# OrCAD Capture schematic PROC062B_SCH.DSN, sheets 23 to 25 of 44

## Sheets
23 22. RGMII ETHERNET PHY - MCU: size C; title: RGMII ETHERNET PHY - MCU
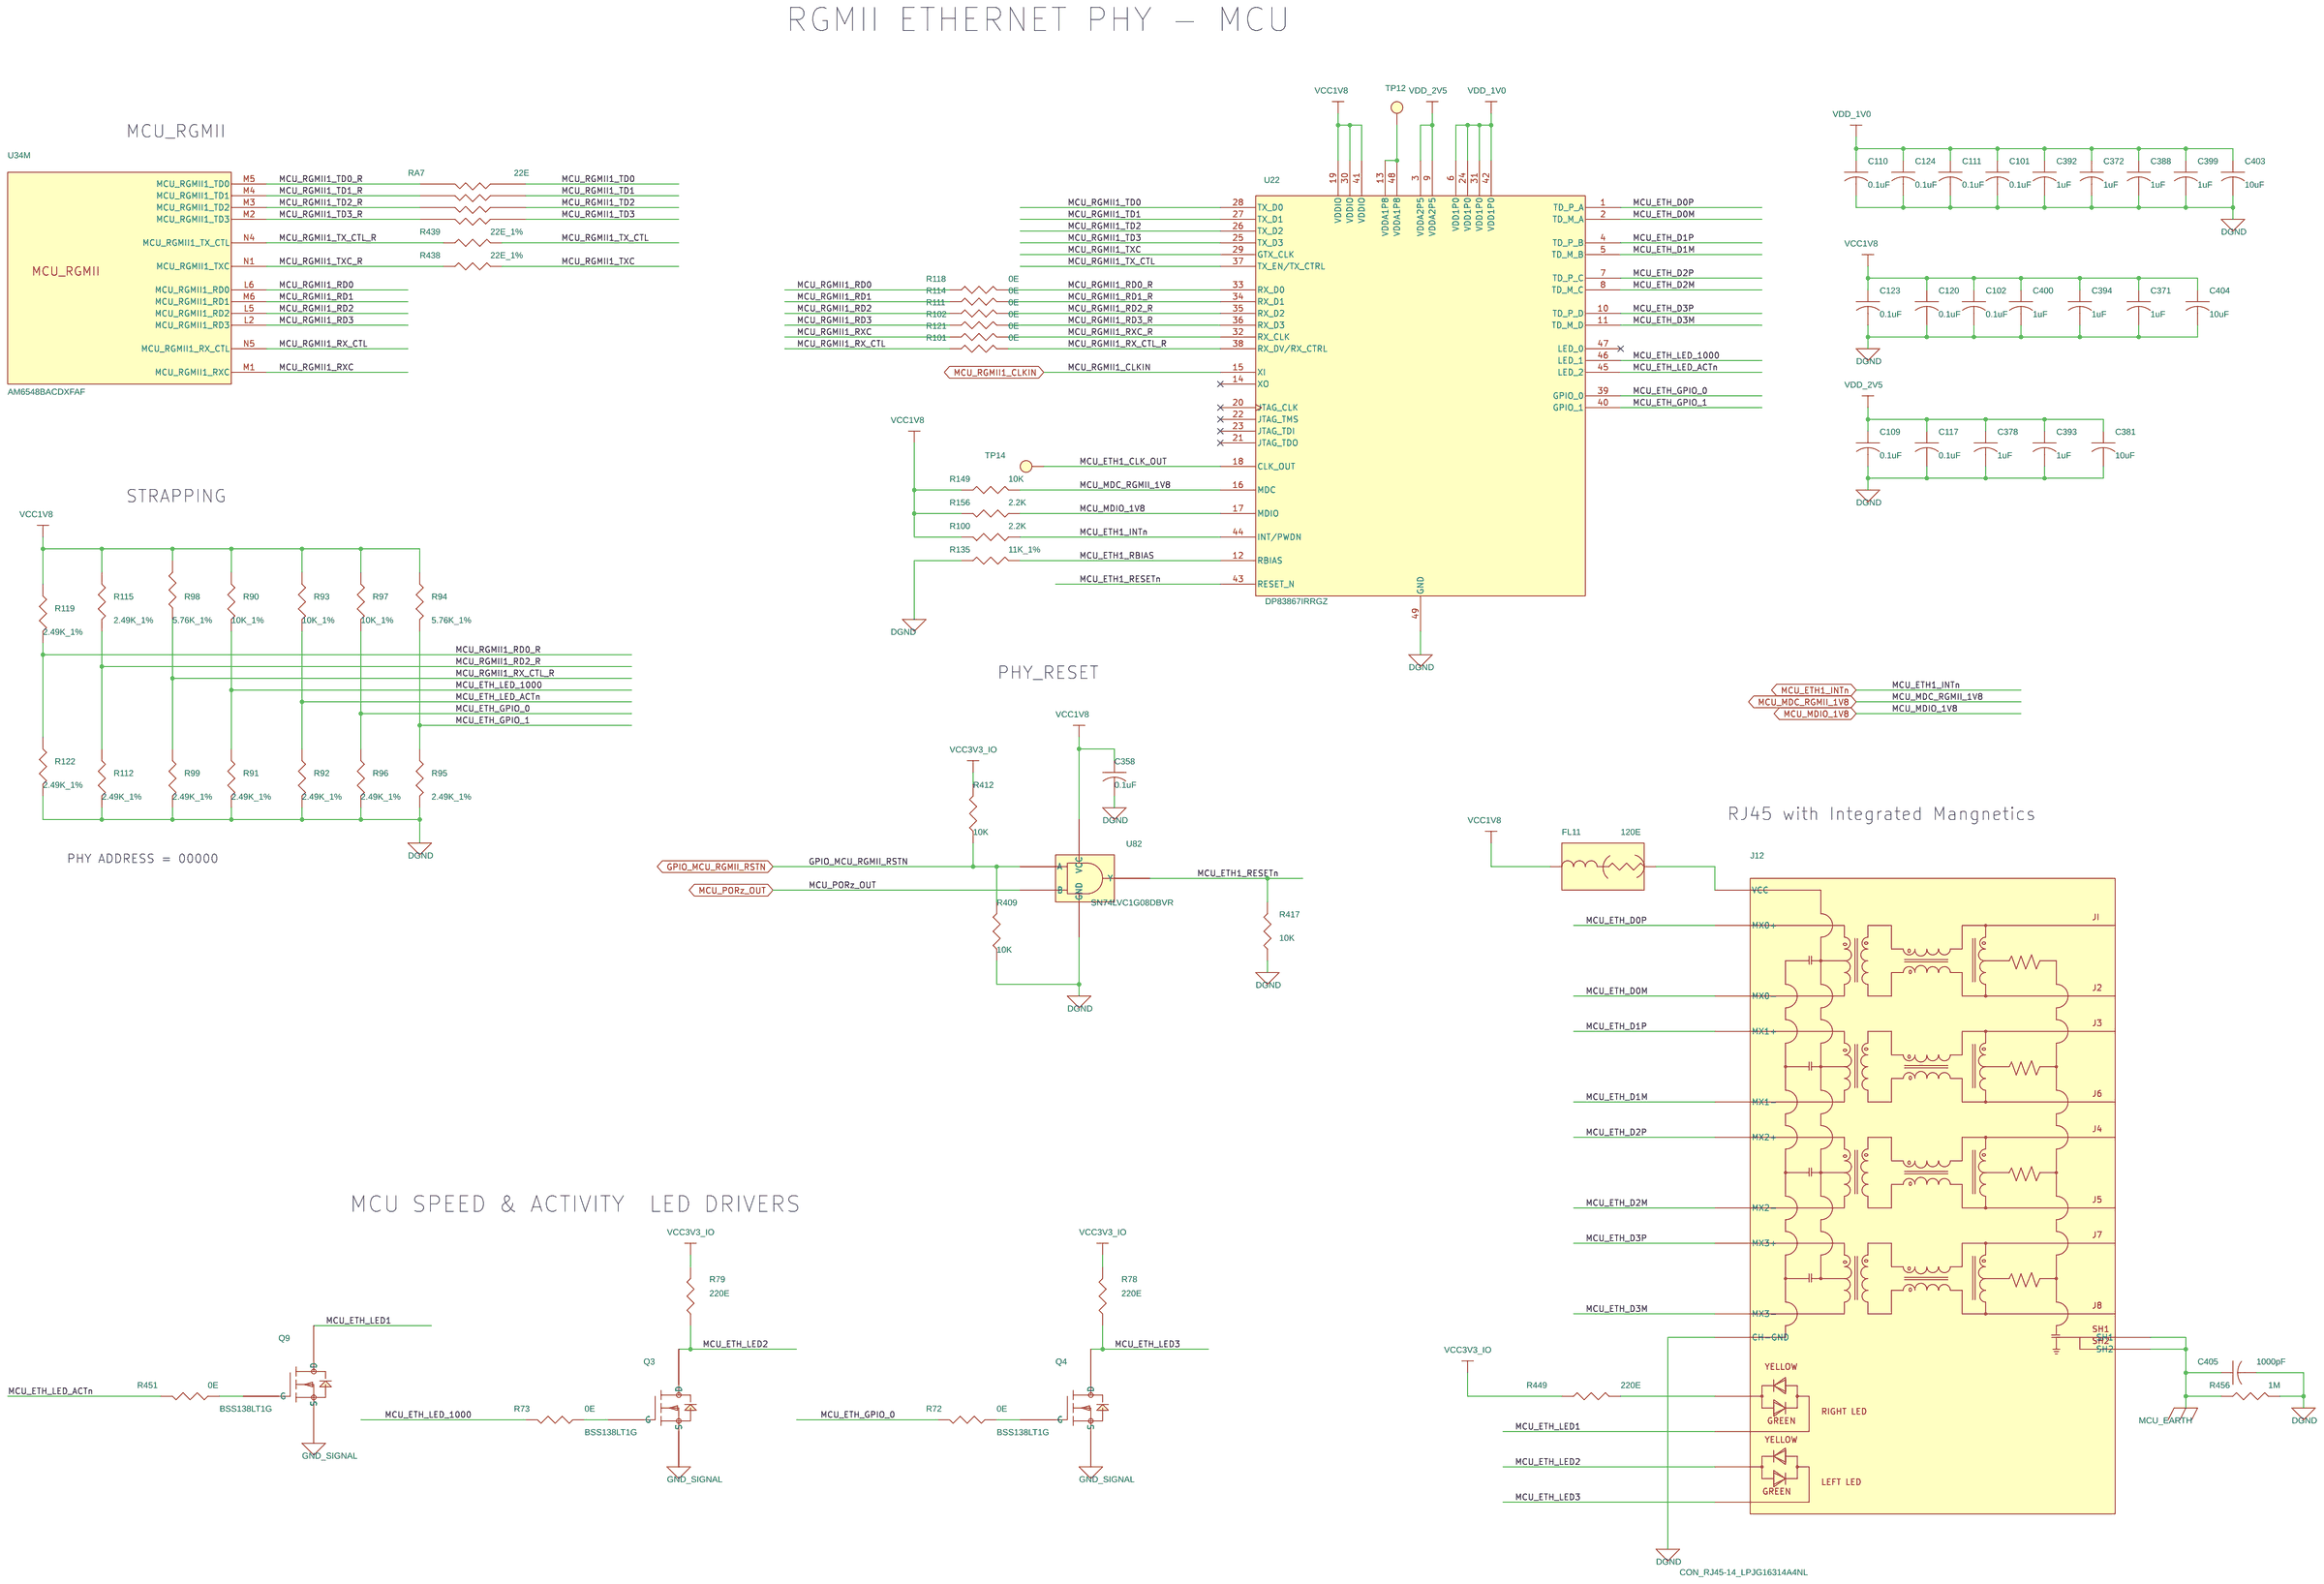
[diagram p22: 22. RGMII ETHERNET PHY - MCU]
24 23. TEST AUTOMATION: size C; title: TEST AUTOMATION
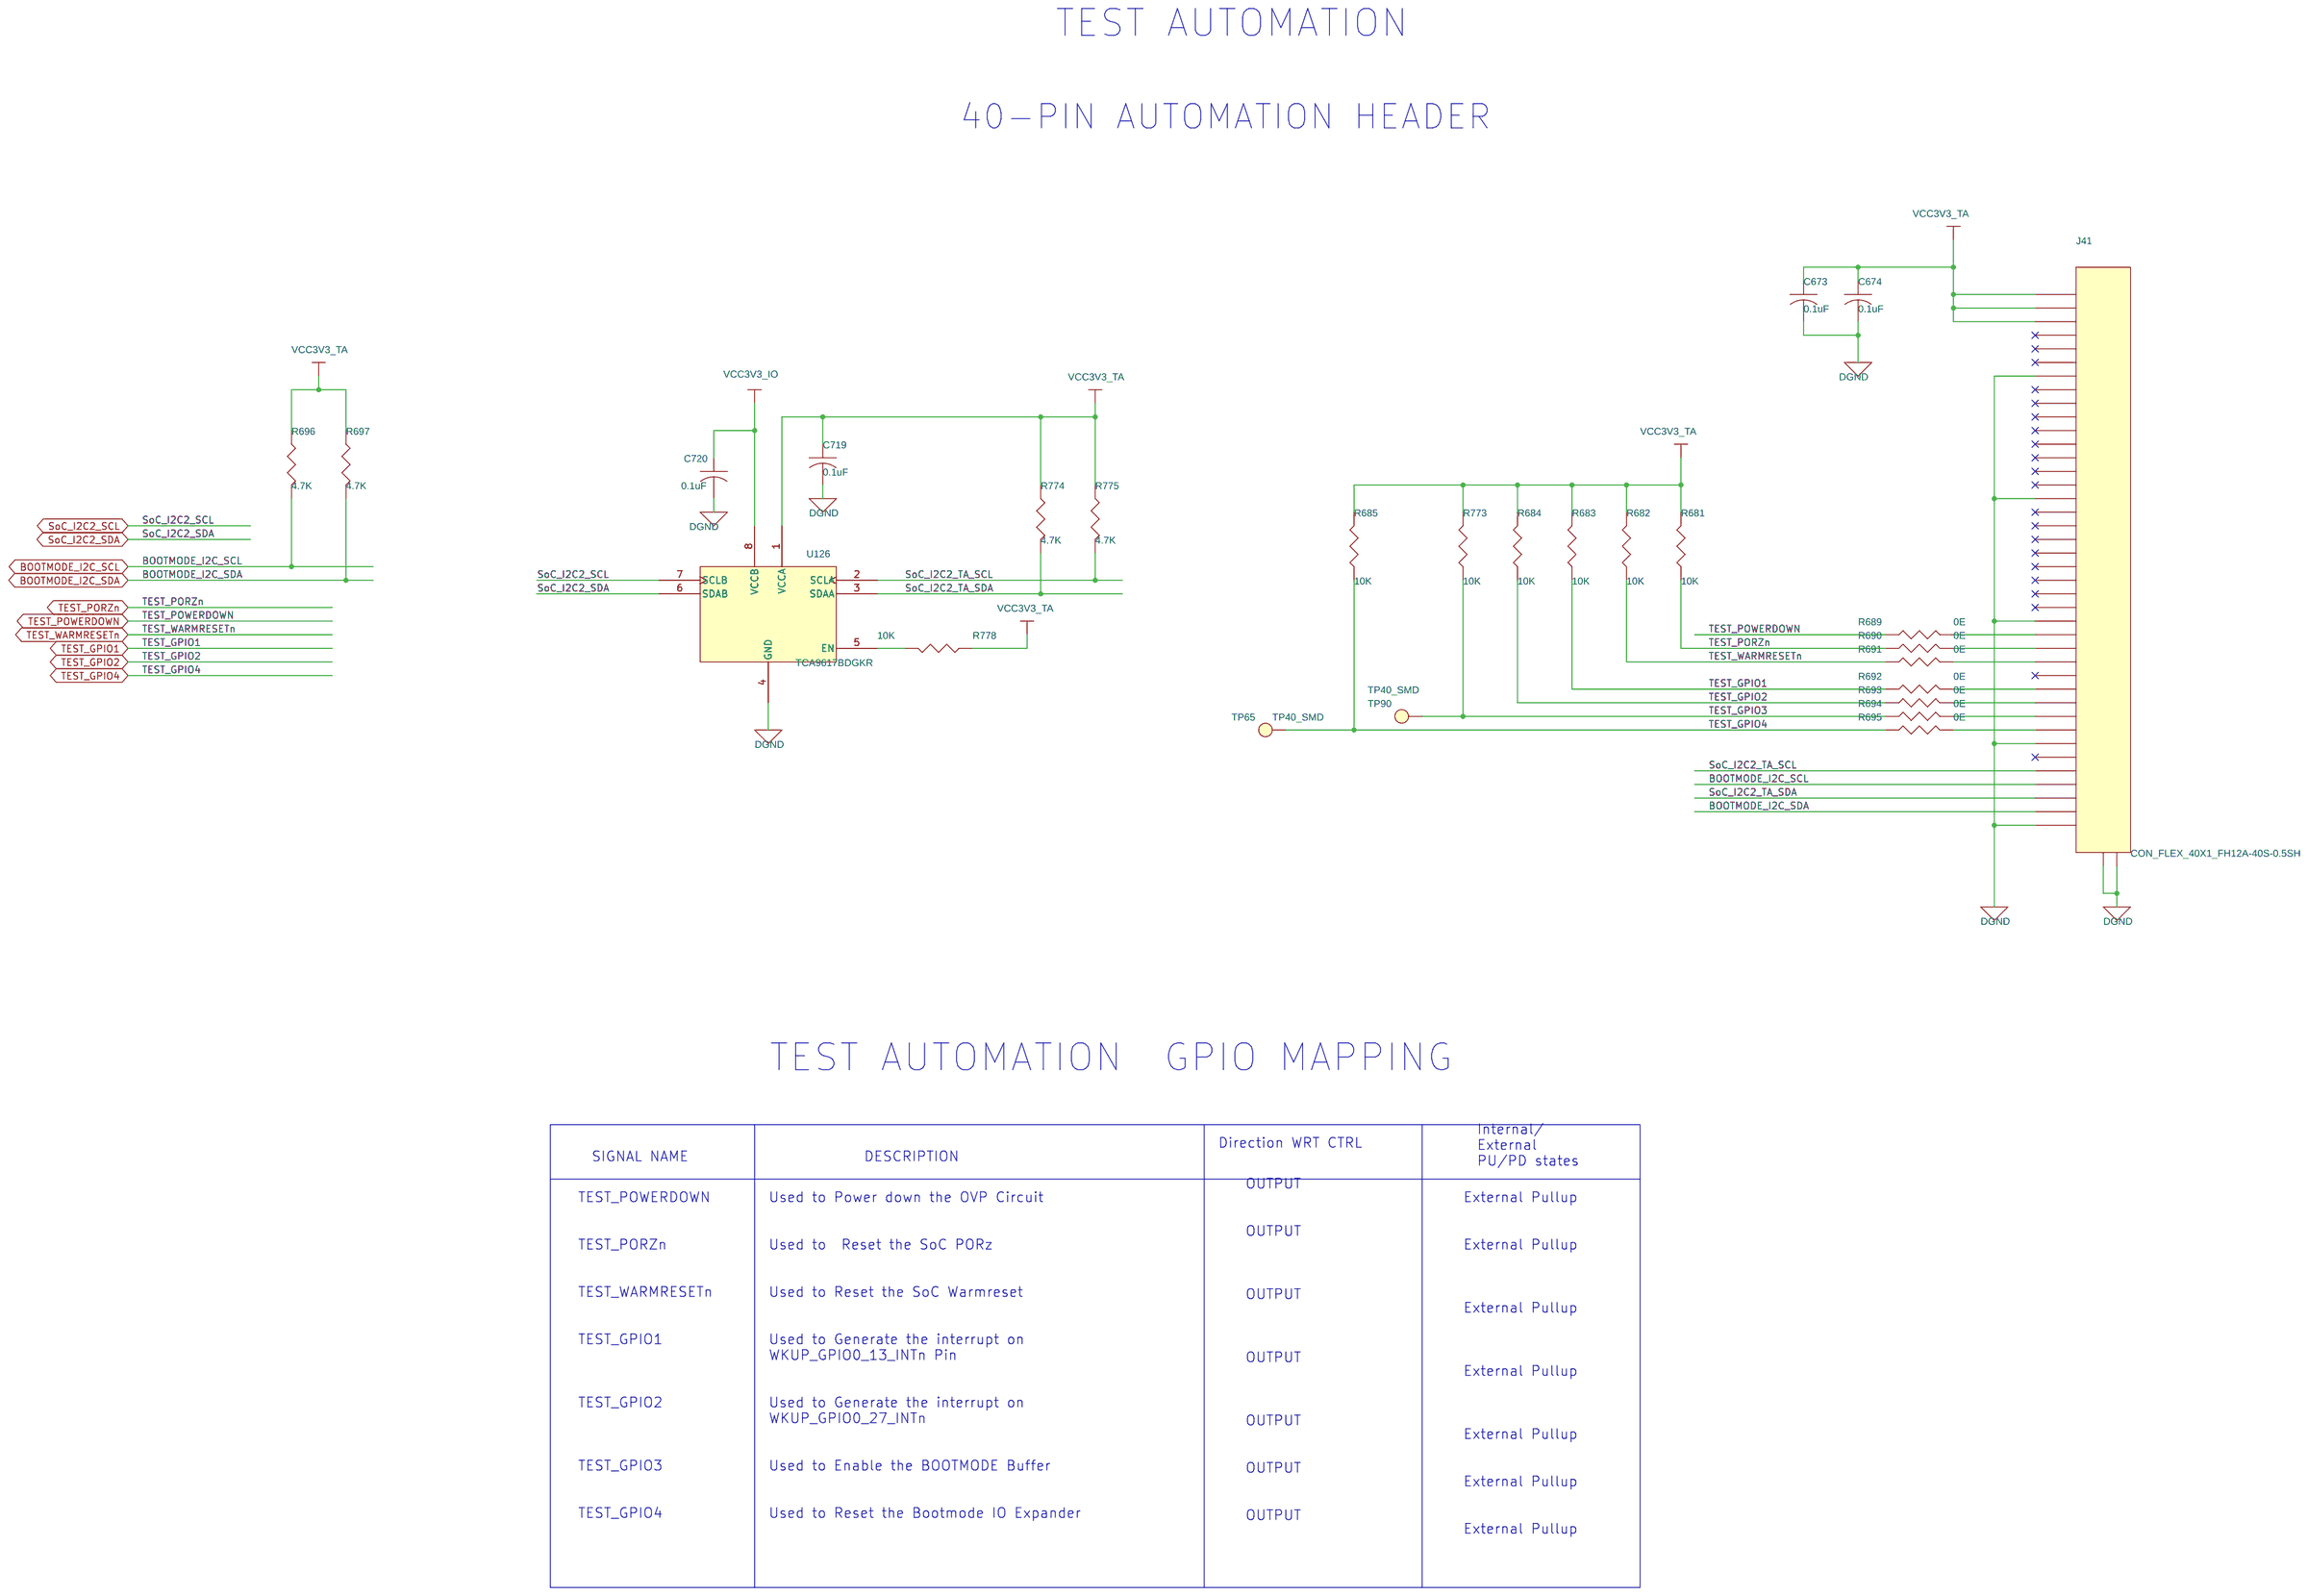
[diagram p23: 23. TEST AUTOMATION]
25 24. BOOT MODE BUFFER & SWITCHES: size C; title: BOOT MODE BUFFER & SWITCHES
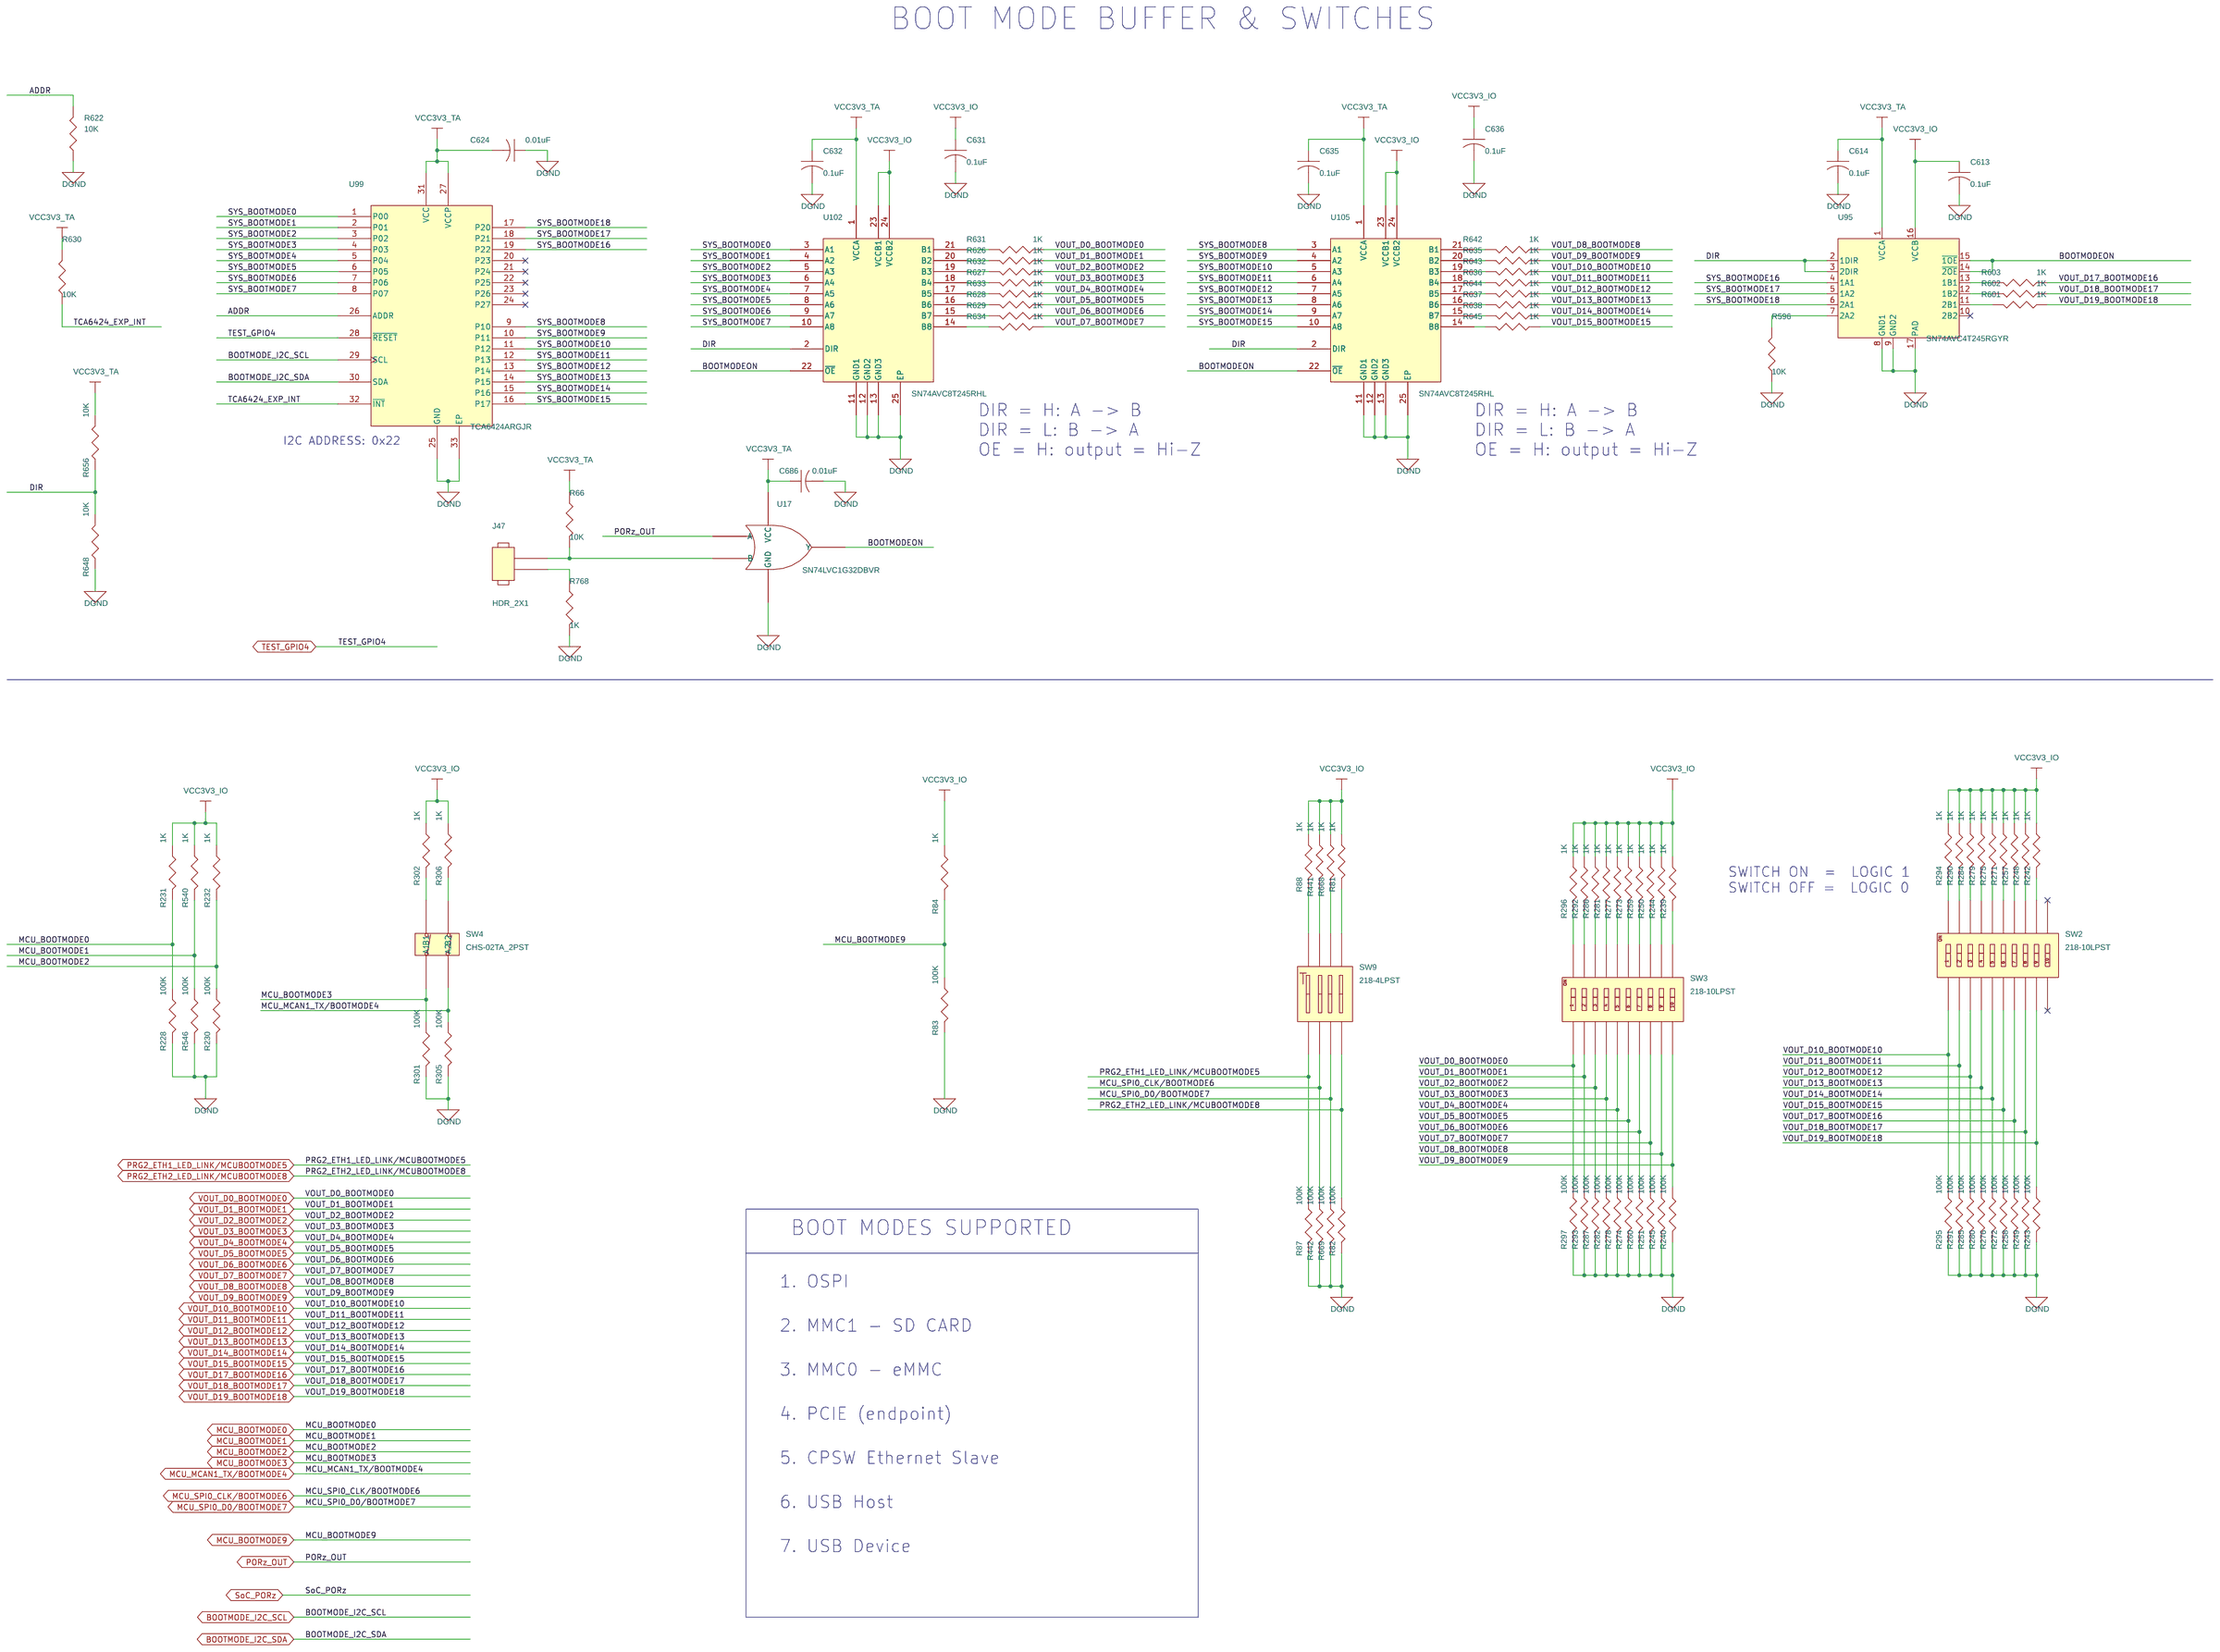
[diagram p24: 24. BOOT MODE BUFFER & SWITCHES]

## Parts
sheet 16. DDR4 ECC & TERMINATIONS
U34  AM6548BACDXFAF  [BGA784_31-49_910X910_1-7]  (sections A,B,C,D,E,F,G,H,I,J,K,L,M,N,O,P,Q,R,S)
sheet 22. RGMII ETHERNET PHY - MCU
C101  0.1uF  [CAP0201_0-5]
C102  0.1uF  [CAP0201_0-5]
C109  0.1uF  [CAP0201_0-5]
C110  0.1uF  [CAP0201_0-5]
C111  0.1uF  [CAP0201_0-5]
C117  0.1uF  [CAP0201_0-5]
C120  0.1uF  [CAP0201_0-5]
C123  0.1uF  [CAP0201_0-5]
C124  0.1uF  [CAP0201_0-5]
C358  0.1uF  [CAP0201_0-5]
C371  1uF  [CAP0402_0-75]
C372  1uF  [CAP0402_0-75]
C378  1uF  [CAP0402_0-75]
C381  10uF  [CAP0603_1]
C388  1uF  [CAP0402_0-75]
C392  1uF  [CAP0402_0-75]
C393  1uF  [CAP0402_0-75]
C394  1uF  [CAP0402_0-75]
C399  1uF  [CAP0402_0-75]
C400  1uF  [CAP0402_0-75]
C403  10uF  [CAP0603_1]
C404  10uF  [CAP0603_1]
C405  1000pF  [CAP1206]
FL11  120E  [EMIFIL_BLM15A_0402_0-6]
J12  CON_RJ45-14_LPJG16314A4NL  [CON_RJ45-14_LPJG16314A4NL_S_R_T_13-6]
Q3  BSS138LT1G  [SOT23-123]
Q4  BSS138LT1G  [SOT23-123]
Q9  BSS138LT1G  [SOT23-123]
R72  0E  [RES0402_0-5]
R73  0E  [RES0402_0-5]
R78  220E  [RES0402_0-5]
R79  220E  [RES0402_0-5]
R90  10K_1%  [RES0402_0-5]
R91  2.49K_1%  [RES0402]
R92  2.49K_1%  [RES0402]
R93  10K_1%  [RES0402_0-5]
R94  5.76K_1%  [RES0402]
R95  2.49K_1%  [RES0402]
R96  2.49K_1%  [RES0402]
R97  10K_1%  [RES0402_0-5]
R98  5.76K_1%  [RES0402]
R99  2.49K_1%  [RES0402]
R100  2.2K  [RES0402_0-5]
R101  0E  [RES0402_0-5]
R102  0E  [RES0402_0-5]
R111  0E  [RES0402_0-5]
R112  2.49K_1%  [RES0402]
R114  0E  [RES0402_0-5]
R115  2.49K_1%  [RES0402]
R118  0E  [RES0402_0-5]
R119  2.49K_1%  [RES0402]
R121  0E  [RES0402_0-5]
R122  2.49K_1%  [RES0402]
R135  11K_1%  [RES0402_0-5]
R149  10K  [RES0201]
R156  2.2K  [RES0402_0-5]
R409  10K  [RES0402_0-5]
R412  10K  [RES0402_0-5]
R417  10K  [RES0402_0-5]
R438  22E_1%  [RES0402]
R439  22E_1%  [RES0402]
R449  220E  [RES0402_0-5]
R451  0E  [RES0402_0-5]
R456  1M  [RES0603_0-75]
RA7  22E  [RESA_EXB28V_0402-4_0-5]
TP12  TP40_SMD  [TP40_SMD]
TP14  TP40_SMD  [TP40_SMD]
U22  DP83867IRRGZ  [QFN48_19-68_280X280_1]
U82  SN74LVC1G08DBVR  [SOT23-5]
sheet 23. TEST AUTOMATION
C673  0.1uF  [CAP0201_0-5]
C674  0.1uF  [CAP0201_0-5]
C719  0.1uF  [CAP0201_0-5]
C720  0.1uF  [CAP0201_0-5]
J41  CON_FLEX_40X1_FH12A-40S-0.5SH  [CON_FLEX40X1_FH12A_S_R_S]
R681  10K  [RES0402_0-5]
R682  10K  [RES0402_0-5]
R683  10K  [RES0402_0-5]
R684  10K  [RES0402_0-5]
R685  10K  [RES0402_0-5]
R689  0E  [RES0402_0-5]
R690  0E  [RES0402_0-5]
R691  0E  [RES0402_0-5]
R692  0E  [RES0402_0-5]
R693  0E  [RES0402_0-5]
R694  0E  [RES0402_0-5]
R695  0E  [RES0402_0-5]
R696  4.7K  [RES0402]
R697  4.7K  [RES0402]
R773  10K  [RES0402_0-5]
R774  4.7K  [RES0402]
R775  4.7K  [RES0402]
R778  10K  [RES0402_0-5]
TP65  TP40_SMD  [TP40_SMD]
TP90  TP40_SMD  [TP40_SMD]
U126  TCA9617BDGKR  [VSSOP8_25-59_120X120_1-1]
sheet 24. BOOT MODE BUFFER & SWITCHES
C613  0.1uF  [CAP0201_0-5]
C614  0.1uF  [CAP0201_0-5]
C624  0.01uF  [CAP0201_0-5]
C631  0.1uF  [CAP0201_0-5]
C632  0.1uF  [CAP0201_0-5]
C635  0.1uF  [CAP0201_0-5]
C636  0.1uF  [CAP0201_0-5]
C686  0.01uF  [CAP0201_0-5]
J47  HDR_2X1  [HDR_2X1_100_S_T_10-8]
R66  10K  [RES0402_0-5]
R81  1K  [RES0201]
R82  100K  [RES0402_0-5]
R83  100K  [RES0402_0-5]
R84  1K  [RES0402]
R87  100K  [RES0402_0-5]
R88  1K  [RES0201]
R228  100K  [RES0402_0-5]
R230  100K  [RES0402_0-5]
R231  1K  [RES0201]
R232  1K  [RES0201]
R239  1K  [RES0201]
R240  100K  [RES0402_0-5]
R242  1K  [RES0201]
R243  100K  [RES0402_0-5]
R244  1K  [RES0201]
R245  100K  [RES0402_0-5]
R248  1K  [RES0201]
R249  100K  [RES0402_0-5]
R250  1K  [RES0201]
R251  100K  [RES0402_0-5]
R257  1K  [RES0201]
R258  100K  [RES0402_0-5]
R259  1K  [RES0201]
R260  100K  [RES0402_0-5]
R271  1K  [RES0201]
R272  100K  [RES0402_0-5]
R273  1K  [RES0201]
R274  100K  [RES0402_0-5]
R275  1K  [RES0201]
R276  100K  [RES0402_0-5]
R277  1K  [RES0201]
R278  100K  [RES0402_0-5]
R279  1K  [RES0201]
R280  100K  [RES0402_0-5]
R281  1K  [RES0201]
R282  100K  [RES0402_0-5]
R284  1K  [RES0201]
R285  100K  [RES0402_0-5]
R286  1K  [RES0201]
R287  100K  [RES0402_0-5]
R290  1K  [RES0201]
R291  100K  [RES0402_0-5]
R292  1K  [RES0201]
R293  100K  [RES0402_0-5]
R294  1K  [RES0201]
R295  100K  [RES0402_0-5]
R296  1K  [RES0201]
R297  100K  [RES0402_0-5]
R301  100K  [RES0402_0-5]
R302  1K  [RES0201]
R305  100K  [RES0402_0-5]
R306  1K  [RES0201]
R441  1K  [RES0201]
R442  100K  [RES0402_0-5]
R540  1K  [RES0201]
R546  100K  [RES0402_0-5]
R596  10K  [RES0402_0-5]
R601  1K  [RES0201]
R602  1K  [RES0201]
R603  1K  [RES0201]
R622  10K  [RES0402_0-5]
R626  1K  [RES0201]
R627  1K  [RES0201]
R628  1K  [RES0201]
R629  1K  [RES0201]
R630  10K  [RES0402_0-5]
R631  1K  [RES0201]
R632  1K  [RES0201]
R633  1K  [RES0201]
R634  1K  [RES0201]
R635  1K  [RES0201]
R636  1K  [RES0201]
R637  1K  [RES0201]
R638  1K  [RES0201]
R642  1K  [RES0201]
R643  1K  [RES0201]
R644  1K  [RES0201]
R645  1K  [RES0201]
R648  10K  [RES0402_0-5]
R656  10K  [RES0402_0-5]
R668  1K  [RES0201]
R669  100K  [RES0402_0-5]
R768  1K  [RES0201]
SW2  218-10LPST  [SW10_50_550X230_SMD]
SW3  218-10LPST  [SW10_50_550X230_SMD]
SW4  CHS-02TA_2PST  [SW2_50x200_160x210_SMD]
SW9  218-4LPST  [SW8_218-4LPS_230X250_SMD_2-7]
U17  SN74LVC1G32DBVR  [SOT23-5_1-5]
U95  SN74AVC4T245RGYR  [QFN16_19-68_160X140]
U99  TCA6424ARGJR  [QFN32_19-68_200X200]
U102  SN74AVC8T245RHL  [QFN24_19-68_220X140_1]
U105  SN74AVC8T245RHL  [QFN24_19-68_220X140_1]

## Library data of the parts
U34 = AM654X_BGA784: IC AM65X MICRO CONTROLLER UNIT BGA784; Chkd/date: ALVY/010721; Crtd /date: MANIRAJA/010721; Custom_Duty: 15%; Customs_HS_Code: 85423100; Distributor_name: NA; Distributor_part_number: NA; Footprint Path: Y:\MIS_DATABASE\Library\ALTIUM_TOOL\PCB_FOOTPRINTS\Altium_Footprint_Lib.PcbLib; Height: 1.63MM; Library Path: Y:\MIS_DATABASE\Library\ALTIUM_TOOL\SCHEMATICS_PARTS\MS_MICROCONTROLLER_Library.schlib; Mfr_name: TEXAS INSTRUMENTS; Mistral Part No: 141221070001; Package: BGA784; Part_type: ICS\DIGITAL\MICROCONTROLLER; Project: TI_AM65X_CP; RoHS: NA; Temperature: NA; Tolerance: NA; Voltage: NA; Wattage: NA; Weight: NA; Datasheet: Y:\MIS_DATABASE\DATASHEETS\ICS\DIGITAL\MICROCONTROLLER\MAXWELLM4.PDF
C101 C102 C109-C111 C117 C120 C123 C124 C358 C613 C614 C631 C632 C635 C636 C673 C674 C719 C720 = CAP: CAP CERAMIC 0.1uF 16V 10% X5R 0201; Chkd/date: MANIRAJA/120218; Crtd /date: MANIRAJA/120218; Custom_Duty: 15%; Customs_HS_Code: 85322990; Distributor_name: DIGIKEY; Distributor_part_number: 490-16742-1-ND; Height: 0.33MM; Mfr_name: MURATA; Mfr_part_number: GRM033R61C104KE84J; Mistral Part No: 120009030072-R; Package: 0201; Part_type: CAPACITORS\CERAMIC; Project: TI_MAXIE_CPB; RoHS: RoHS; Temperature: -55°C+85°C; Tolerance: 10%; Voltage: 16V; Wattage: NA; Weight: 0.33mg; Datasheet: Y:\MIS_DATABASE\DATASHEETS\CAPACITORS\GRM033R61C104KE84.PDF
C371 C372 C378 C388 C392-C394 C399 C400 = CAP: CAP CERAMIC 1uF 16V 20% X5R 0402; Chkd/date: MANIRAJA/150218; Crtd /date: ALVY/150218; Custom_Duty: 15%; Customs_HS_Code: 85322990; Distributor_name: DIGIKEY; Distributor_part_number: 587-5514-1-ND; Footprint Path: Y:\MIS_DATABASE\Library\ALTIUM_TOOL\PCB_FOOTPRINTS\Altium_Footprint_Lib.PcbLib; Height: 0.55MM; Library Path: Y:\MIS_DATABASE\Library\ALTIUM_TOOL\SCHEMATICS_PARTS\MS_DISCRETE_Library.schlib; Mfr_name: TAIYO YUDEN; Mfr_part_number: EMK105BJ105MV-F; Mistral Part No: 120018020006-R; Package: 0402; Part_type: CAPACITORS\CERAMIC; Project: TI_MAXIE_CPB; RoHS: RoHS; Temperature: -55°C+85°C; Tolerance: 20%; Voltage: 16V; Wattage: NA; Weight: 0.65mg; Datasheet: Y:\MIS_DATABASE\DATASHEETS\CAPACITORS\EMK105BJ105MV-F.PDF
C381 C403 C404 = CAP: CAP CERAMIC 10uF 10V 10% X5R 0603; Chkd/date: MANIRAJA/230118; Crtd /date: MANIRAJA/230118; Custom_Duty: 15%; Customs_HS_Code: 85322990; Distributor_name: DIGIKEY; Distributor_part_number: 478-10766-1-ND; Height: 0.94MM; Mfr_name: AVX CORPORATION; Mfr_part_number: 0603ZD106KAT2A; Mistral Part No: 120010080001-R; Package: 0603; Part_type: CAPACITORS\CERAMIC; Project: TI_MAXIE_CPB; RoHS: RoHS; Temperature: -55°C+85°C; Tolerance: 10%; Voltage: 10V; Wattage: NA; Weight: 2mg; Datasheet: Y:\MIS_DATABASE\DATASHEETS\CAPACITORS\AVX_MLC.PDF
C405 = CAP: CAP CERAMIC 1000pF 2KV 10% X7R 1206; Chkd/date: SHREESHAIL/291106; Crtd /date: MAZHAR/281106; Custom_Duty: 15%; Customs_HS_Code: 85322990; Distributor_name: DIGIKEY; Distributor_part_number: 478-2956-1-ND; Footprint Path: Y:\MIS_DATABASE\Library\ALTIUM_TOOL\PCB_FOOTPRINTS\Altium_Footprint_Lib.PcbLib; Height: 1.50MM; Library Path: Y:\MIS_DATABASE\Library\ALTIUM_TOOL\SCHEMATICS_PARTS\MS_DISCRETE_Library.schlib; Mfr_name: AVX CORPORATION; Mfr_part_number: 1206GC102KAT1A; Mistral Part No: 120009030147-R; Package: 1206; Part_type: CAPACITORS\CERAMIC; Project: ADR1B; RoHS: RoHS; Temperature: -55°C+125°C; Tolerance: 10%; Voltage: 2KV; Weight: NA; Datasheet: Y:\MIS_DATABASE\DATASHEETS\CAPACITORS\AVX_MLC.PDF
FL11 = EMIFILTER_IND: FERRITE CHIP 120E 1.3A 0402; Chkd/date: VASANTHA/010117; Crtd /date: CHAITHANYA/150312; Custom_Duty: 24%; Customs_HS_Code: 85437099; Distributor_name: DIGIKEY; Distributor_part_number: 490-5203-1-ND; Footprint Path: Y:\MIS_DATABASE\Library\ALTIUM_TOOL\PCB_FOOTPRINTS\Altium_Footprint_Lib.PcbLib; Height: 0.55MM; Library Path: Y:\MIS_DATABASE\Library\ALTIUM_TOOL\SCHEMATICS_PARTS\MS_FILTER_Library.schlib; Mfr_name: MURATA; Mfr_part_number: BLM15PD121SN1; Mistral Part No: 130012030043-R; Package: 0402; Part_type: MISC\FILTER; Project: GEN_3-8; RoHS: RoHS; Temperature: -55°C+125°C; Tolerance: 25%; Voltage: NA; Wattage: NA; Weight: 0.65mg; Datasheet: Y:\MIS_DATABASE\DATASHEETS\DISCRETES\INDUCTORS\BLM18K-SERIES.PDF
J12 = CON_RJ45-14_LPJG16314A4NL: CON RJ-45 FEMALE 14POS RT TH; Chkd/date: VASANTHA/150714; Crtd /date: BALACHANDAR/120614; Custom_Duty: 24%; Customs_HS_Code: 85369090; Distributor_name: NA; Distributor_part_number: NA; Footprint Path: Y:\MIS_DATABASE\Library\ALTIUM_TOOL\PCB_FOOTPRINTS\Altium_Footprint_Lib.PcbLib; Height: 13.60MM; Library Path: Y:\MIS_DATABASE\Library\ALTIUM_TOOL\SCHEMATICS_PARTS\MS_CONNECTOR_Library.schlib; Mfr_name: LINK-PP; Mfr_part_number: LPJG16314A4NL; Mistral Part No: 150014060029-R; Package: THRU-HOLE; Part_type: CONNECTOR\JACK; Project: AEGIS; RoHS: RoHS; Temperature: -0°C+70°C; Tolerance: NA; Voltage: NA; Wattage: NA; Weight: NA; Datasheet: Y:\MIS_DATABASE\DATASHEETS\CONNECTORS\LPJG16314A4NL.PDF
Q3 Q4 Q9 = MOSFET_BSS138LT1G: IC MOSFET N-CHANNEL 50V, SOT23-3; Chkd/date: VASANTHA/150416; Crtd /date: JEBRAN/060416; Custom_Duty: 15%; Customs_HS_Code: 85423100; Distributor_name: MOUSER; Distributor_part_number: 863-BSS138LT1G; Height: 1.11MM; Mfr_name: ON SEMICONDUCTOR; Mistral Part No: 142016040001-R; Package: SOT23-3; Part_type: ICS\POWER\MOSFET; Project: LRDE_ABCM; RoHS: RoHS; Temperature: -55°C+150°C; Tolerance: NA; Voltage: 50V; Wattage: NA; Weight: NA; Datasheet: Y:\MIS_DATABASE\DATASHEETS\DISCRETES\TRANSISTORS_FETS\BSS138LT1G.PDF
R72 R73 R101 R102 R111 R114 R118 R121 R451 R689-R695 = RESISTOR: RES 0E 1/16W 0402; Chkd/date: VASANTHA/201216; Crtd /date: MUDDU/190810; Custom_Duty: 15%; Customs_HS_Code: 85332119; Distributor_name: DIGIKEY; Distributor_part_number: 541-0.0JCT-ND; Footprint Path: Y:\MIS_DATABASE\Library\ALTIUM_TOOL\PCB_FOOTPRINTS\Altium_Footprint_Lib.PcbLib; Height: 0.40MM; Library Path: Y:\MIS_DATABASE\Library\ALTIUM_TOOL\SCHEMATICS_PARTS\MS_DISCRETE_Library.schlib; Mfr_name: VISHAY; Mfr_part_number: CRCW04020000Z0ED; Mistral Part No: 110010080019-P; Package: 0402; Part_type: RESISTORS\FIXED; Project: PB_BUGBASE; RoHS: Pb-Free; Temperature: -55°C+155°C; Tolerance: NA; Voltage: NA; Wattage: 1/16W; Weight: 0.65g/1000pcs; Datasheet: Y:\MIS_DATABASE\DATASHEETS\RESISTORS\CRCW0603.PDF
R78 R79 R449 = RESISTOR: RES 220E 1/16W 5% 0402; Chkd/date: VASANTHA/291216; Crtd /date: GEETHA/260406; Custom_Duty: 15%; Customs_HS_Code: 85332119; Distributor_name: DIGIKEY; Distributor_part_number: P220JCT-ND; Footprint Path: Y:\MIS_DATABASE\Library\ALTIUM_TOOL\PCB_FOOTPRINTS\Altium_Footprint_Lib.PcbLib; Height: 0.40MM; Library Path: Y:\MIS_DATABASE\Library\ALTIUM_TOOL\SCHEMATICS_PARTS\MS_DISCRETE_Library.schlib; Mfr_name: PANASONIC-ECG; Mfr_part_number: ERJ-2GEJ221X; Mistral Part No: 110009030506-R; Package: 0402; Part_type: RESISTORS\FIXED; Project: RED EYE; RoHS: RoHS; Temperature: -55°C+155°C; Tolerance: 5%; Voltage: NA; Wattage: 1/16W; Weight: 0.8g/1000pcs; Datasheet: Y:\MIS_DATABASE\DATASHEETS\RESISTORS\ERJ12.PDF
R90 R93 R97 = RESISTOR: RES 10K 1/16W 1% 0402; Chkd/date: VASANTHA/201216; Crtd /date: GEETHA/290506; Custom_Duty: 15%; Customs_HS_Code: 85332119; Distributor_name: DIGIKEY; Distributor_part_number: 311-10.0KLRTR-ND; Footprint Path: Y:\MIS_DATABASE\Library\ALTIUM_TOOL\PCB_FOOTPRINTS\Altium_Footprint_Lib.PcbLib; Height: 0.40MM; Library Path: Y:\MIS_DATABASE\Library\ALTIUM_TOOL\SCHEMATICS_PARTS\MS_DISCRETE_Library.schlib; Mfr_name: YAGEO AMERICA; Mfr_part_number: RC0402FR-0710KL; Mistral Part No: 110009030220-P; Package: 0402; Part_type: RESISTORS\FIXED; Project: VOCERA; RoHS: Pb-Free; Temperature: -55°C+155°C; Tolerance: 1%; Voltage: NA; Wattage: 1/16W; Weight: 0.65mg; Datasheet: Y:\MIS_DATABASE\DATASHEETS\RESISTORS\YAGEO-RC0402.PDF
R91 R92 R95 R96 R99 R112 R115 R119 R122 = RESISTOR: RES 2.49K 1/16W 1% 0402; Chkd/date: VASANTHA/270516; Crtd /date: VASANTHA/270516; Custom_Duty: 15%; Customs_HS_Code: 85332119; Distributor_name: DIGIKEY; Distributor_part_number: 311-2.49KLRCT-ND; Height: 0.40MM; Mfr_name: YAGEO AMERICA; Mfr_part_number: RC0402FR-072K49L; Mistral Part No: 110016050020-R; Package: 0402; Part_type: RESISTORS\FIXED; Project: TMDXCSKCC; RoHS: RoHS; Temperature: -55°C+155°C; Tolerance: 1%; Voltage: NA; Wattage: 1/16W; Weight: NA; Datasheet: Y:\MIS_DATABASE\DATASHEETS\RESISTORS\RC0402FR.PDF
R94 R98 = RESISTOR: RES 5.76K 1/10W 1% 0402; Chkd/date: MAZHAR/150709; Crtd /date: USMAN/220808; Custom_Duty: 15%; Customs_HS_Code: 85332119; Distributor_name: DIGIKEY; Distributor_part_number: P5.76KLCT-ND; Footprint Path: Y:\MIS_DATABASE\Library\ALTIUM_TOOL\PCB_FOOTPRINTS\Altium_Footprint_Lib.PcbLib; Height: 0.40MM; Library Path: Y:\MIS_DATABASE\Library\ALTIUM_TOOL\SCHEMATICS_PARTS\MS_DISCRETE_Library.schlib; Mfr_name: PANASONIC-ECG; Mfr_part_number: ERJ-2RKF5761X; Mistral Part No: 110009030945-R; Package: 0402; Part_type: RESISTORS\FIXED; Project: CPB; RoHS: RoHS; Tolerance: 1%; Wattage: 1/10W; Datasheet: Y:\MIS_DATABASE\DATASHEETS\RESISTORS\PAN-ERJSERIES.PDF
R100 R156 = RESISTOR: RES 2.2K 1/16W 5% 0402; Chkd/date: VASANTHA/061216; Crtd /date: BAVISH/021210; Custom_Duty: 15%; Customs_HS_Code: 85332119; Distributor_name: DIGIKEY; Distributor_part_number: 311-2.2KJRCT-ND; Footprint Path: VALUE IS VAILABLE 3 TIMES; Height: 0.40MM; Mfr_name: YAGEO AMERICA; Mfr_part_number: RC0402JR-072K2L; Mistral Part No: 110010120018-R; Package: 0402; Part_type: RESISTORS\FIXED; Project: TE4; RoHS: RoHS; Temperature: -55°C+155°C; Tolerance: 5%; Voltage: NA; Wattage: 1/16W; Weight: 0.65mg; Datasheet: Y:\MIS_DATABASE\DATASHEETS\RESISTORS\YAGEO.PDF
R135 = RESISTOR: RES 11K 1/16W 1% 0402; Chkd/date: VASANTHA/251115; Crtd /date: VASANTHA/251115; Custom_Duty: 15%; Customs_HS_Code: 85332119; Distributor_name: DIGIKEY; Distributor_part_number: 311-11.0KLRCT-ND; Height: 0.40MM; Mfr_name: YAGEO AMERICA; Mfr_part_number: RC0402FR-0711KL; Mistral Part No: 110015110012-P; Package: 0402; Part_type: RESISTORS\FIXED; Project: TI_VLAN_SWITCH; RoHS: Pb-Free; Temperature: -55°C+155°C; Tolerance: 1%; Voltage: NA; Wattage: 1/16W; Weight: 0.65mg; Datasheet: Y:\MIS_DATABASE\DATASHEETS\RESISTORS\YAGEO-RC0402.PDF
R149 = RESISTOR: RES 10K 1/20W 5% 0201; Alternate_mfr_name_A: KOA SPEER; Alternate_mfr_part_number_A: RK73B1HTTC103J; Chkd/date: SUHAS/280910; Crtd /date: MUDDU/100710; Custom_Duty: 15%; Customs_HS_Code: 85332119; Distributor_name: NA; Distributor_name_A: NA; Distributor_part_number: NA; Distributor_part_number_A: NA; Height: 0.30MM; Mfr_name: NIC COMPONENTS; Mfr_part_number: NRC02J103TRF; Mistral Part No: 110010070051-R; Package: 0201; Part_type: RESISTORS\FIXED; Project: PB_BUGBASE; RoHS: RoHS; Temperature: -55°C+125°C; Tolerance: 5%; Voltage: 50V; Wattage: 1/20W; Weight: NA; Datasheet: Y:\MIS_DATABASE\DATASHEETS\RESISTORS\NRC SERIES.PDF
R66 R409 R412 R417 R596 R622 R630 R648 R656 R681-R685 R773 R778 = RESISTOR: RES 10K 1/16W 5% 0402; Chkd/date: VASANTHA/061216; Crtd /date: MAZHAR/230805; Custom_Duty: 15%; Customs_HS_Code: 85332119; Distributor_name: DIGIKEY; Distributor_part_number: 311-10KJRCT-ND; Footprint Path: Y:\MIS_DATABASE\Library\ALTIUM_TOOL\PCB_FOOTPRINTS\Altium_Footprint_Lib.PcbLib; Height: 0.40MM; Library Path: Y:\MIS_DATABASE\Library\ALTIUM_TOOL\SCHEMATICS_PARTS\MS_DISCRETE_Library.schlib; Mfr_name: YAGEO AMERICA; Mfr_part_number: RC0402JR-0710KL; Mistral Part No: 110009030208-R; Package: 0402; Part_type: RESISTORS\FIXED; Project: HSE; RoHS: Pb-Free; Temperature: -55°C+155°C; Tolerance: 5%; Voltage: NA; Wattage: 1/16W; Weight: 0.65mg; Datasheet: Y:\MIS_DATABASE\DATASHEETS\RESISTORS\YAGEO-RC0402.PDF
R438 R439 = RESISTOR: RES 22E 1/16W 1% 0402; Alternate_mfr_name_A: VISHAY; Alternate_mfr_part_number_A: CRCW040222R0FKED; Chkd/date: SUHAS/290910; Crtd /date: MAZHAR/090909; Cust_part_number: 4700-80047E; Custom_Duty: 15%; Customs_HS_Code: 85332119; Distributor_name: DIGIKEY; Distributor_name_A: DIGIKEY; Distributor_part_number: 311-22.0LRCT-ND; Distributor_part_number_A: 541-22.0LCT-ND; Height: 0.40MM; Mfr_name: YAGEO AMERICA; Mfr_part_number: RC0402FR-0722RL; Mistral Part No: 110009090004-P; Package: 0402; Part_type: RESISTORS\FIXED; Project: VMEFMCD; Remarks: In alternate datasheet it is RoHS COMPLIANT. Y:\MIS_DATABASE\DATASHEETS\RESISTORS\CRCW0402.PDF; RoHS: Pb-Free; SIGNAL_MODEL: RESISTOR_RES0402_22E_22E; Temperature: -55°C+155°C; Tolerance: 1%; Voltage: 50V; Wattage: 1/16W; Weight: 0.8g/1000pcs; Datasheet: Y:\MIS_DATABASE\DATASHEETS\RESISTORS\YAGEO-RC0402.PDF
R456 = RESISTOR: RES 1M 1/10W 5% 0603; Chkd/date: VASANTHA/060217; Crtd /date: USMAN/111207; Custom_Duty: 15%; Customs_HS_Code: 85332119; Distributor_name: DIGIKEY; Distributor_part_number: P1.0MGCT-ND; Height: 0.55MM; Mfr_name: PANASONIC-ECG; Mfr_part_number: ERJ-3GEYJ105V; Mistral Part No: 110009030413-R; Package: 0603; Part_type: RESISTORS\FIXED; Project: BSN; RoHS: RoHS; Temperature: -55°C+155°C; Tolerance: 5%; Voltage: NA; Wattage: 1/10W; Weight: 2mg; Datasheet: Y:\MIS_DATABASE\DATASHEETS\RESISTORS\PAN-ERJ-3GE.PDF
RA7 = RESARR_ISO4: RES ARRAY 22E 31mW 5% 0402; Chkd/date: MAZHAR/291208; Crtd /date: USMAN/261108; Distributor_name: DIGIKEY; Distributor_part_number: Y7220CT-ND; Height: 0.45MM; Mfr_name: PANASONIC-ECG; Mfr_part_number: EXB-28V220JX; Mistral Part No: 110009030021-R; Package: 0402; Part_type: RESISTORS\ARRAY; Project: KHAN_MAIN; RoHS: RoHS; Temperature: -55°C+125°C; Tolerance: 5%; Voltage: NA; Wattage: 31mW; Weight: 2mg; Datasheet: Y:\MIS_DATABASE\DATASHEETS\RESISTORS\EXB-2HV.PDF
TP12 TP14 TP65 TP90 = TESTPOINT: TESTPOINT CIR 40 SMD; Chkd/date: MAZHAR/190505; Crtd /date: MAZHAR/190505; Distributor_name: NA; Distributor_part_number: NA; Footprint Path: Y:\MIS_DATABASE\Library\ALTIUM_TOOL\PCB_FOOTPRINTS\Altium_Footprint_Lib.PcbLib; Height: NA; Library Path: Y:\MIS_DATABASE\Library\ALTIUM_TOOL\SCHEMATICS_PARTS\MS_DISCRETE_Library.schlib; MECHANICAL 3D STEP FILE: NA; Mfr_name: LOCAL; Mistral Part No: 130009030933; Package: SMD; Project: RAINIER-3; RoHS: NA; Temperature: NA; Tolerance: NA; Voltage: NA; Wattage: NA; Weight: NA; Datasheet: NA
U22 = DP83867IRRGZ_VQFN48: IC HIGH IMMUNITY 10/100/1000 Mb/s ETHERNET PHY LAYER TRANSCEIVER VQFN48; Chkd/date: MANIRAJA/110817; Crtd /date: MANIRAJA/110817; Custom_Duty: 15%; Customs_HS_Code: 85423100; Distributor_name: DIGIKEY; Distributor_part_number: DP83867IRRGZT-ND; Height: 1.00MM; Mfr_name: TEXAS INSTRUMENTS; Mistral Part No: 143017080002-R; Package: VQFN48; Part_type: ICS\TELECOM\TRANSCEIVER; Project: TI_SVB_CONTROLLER CARD; RoHS: RoHS; Temperature: -40°C+85°C; Tolerance: NA; Voltage: NA; Wattage: NA; Weight: NA; Datasheet: Y:\MIS_DATABASE\DATASHEETS\ICS\DIGITAL\BUSTRANSCEIVER\DP83867I.PDF
U82 = SN74LVC1G08DBVR_SOT23-5: IC SINGLE 2-INPUT POSITIVE AND GATE SOT23-5; Chkd/date: SHREESHAIL/270906; Crtd /date: MAZHAR/270906; Custom_Duty: 15%; Customs_HS_Code: 85423100; Distributor_name: DIGIKEY; Distributor_part_number: 296-11601-1-ND; Height: 1.45MM; Mfr_name: TEXAS INSTRUMENTS; Mistral Part No: 141009030228-R; Part_type: ICS\DIGITAL\GATES; Project: SVDO_RMB_MMA; RoHS: Sb/ Br FREE; Datasheet: Y:\MIS_DATABASE\DATASHEETS\ICS\DIGITAL\GATES\SN74LVC1G08.PDF
J41 = CON_FLEX_40X1_FH12A-40S-0.5SH: CON FPC 40X1 0.50MM PITCH RT TOP SMD; Chkd/date: SHREESHAIL/201106; Crtd /date: MAZHAR/171106; Custom_Duty: 24%; Customs_HS_Code: 85369090; Distributor_name: DIGIKEY; Distributor_part_number: HFK40CT-ND; Height: 2.00MM; Mfr_name: HIROSE ELECTRIC EUROPE; Mfr_part_number: FH12A-40S-0.5SH(55); Mistral Part No: 150009030176-R; Package: SMD; Part_type: CONNECTOR\FPC; Project: PMP LCD BOARD; Remarks: CON_FLEX40X1_FH12A_S_R_S_PMP take this footprint for PMP LCD BOARD/ROHS INFORMATION ADDED(BAVISH/270911)Mistral part# updated with -R.; Datasheet: Y:\MIS_DATABASE\DATASHEETS\CONNECTORS\FH12SERIES.PDF
R696 R697 R774 R775 = RESISTOR: RES 4.7K 1/16W 5% 0402; Chkd/date: VASANTHA/130516; Crtd /date: VASANTHA/130516; Custom_Duty: 15%; Customs_HS_Code: 85332119; Distributor_name: DIGIKEY; Distributor_part_number: 311-4.7KJRCT-ND; Height: 0.55MM; Mfr_name: YAGEO AMERICA; Mfr_part_number: RC0402JR-074K7L; Mistral Part No: 110009030792-R; Package: 0402; Part_type: RESISTORS\FIXED; Project: TMDXCSK368; RoHS: RoHS; Temperature: -55°C+155°C; Tolerance: 5%; Voltage: NA; Wattage: 1/16W; Weight: NA; Datasheet: Y:\MIS_DATABASE\DATASHEETS\RESISTORS\YAGEO-RC0402.PDF
U126 = TCA9617BDGKR_VSSOP8: IC FM+I2C BUS REPEATER LEVEL TRANSLATOR VSSOP8; Chkd/date: MANIRAJA/131017; Crtd /date: MANIRAJA/131017; Custom_Duty: 15%; Customs_HS_Code: 85423100; Distributor_name: DIGIKEY; Distributor_part_number: 296-40579-1-ND; Height: 1.10MM; Mfr_name: TEXAS INSTRUMENTS; Mistral Part No: 141017100010-R; Package: VSSOP8; Part_type: ICS\INTERFACE\LEVEL TRANSLATOR; Project: TI_MAXIE_CPB; RoHS: RoHS; Temperature: -40°C+85°C; Tolerance: NA; Voltage: NA; Wattage: NA; Weight: NA; Datasheet: Y:\MIS_DATABASE\DATASHEETS\ICS\INTERFACE\TCA9617B.PDF
C624 C686 = CAP: CAP CERAMIC 0.01uF 25V 10% X5R 0201; Chkd/date: MANIRAJA/230118; Crtd /date: MANIRAJA/230118; Custom_Duty: 15%; Customs_HS_Code: 85322990; Distributor_name: DIGIKEY; Distributor_part_number: GRM033R61E103KA12J-ND; Height: 0.33MM; Mfr_name: MURATA; Mfr_part_number: GRM033R61E103KA12J; Mistral Part No: 120018010007-R; Package: 0201; Part_type: CAPACITORS\CERAMIC; Project: TI_MAXIE_CPB; RoHS: RoHS; Temperature: -55°C+85°C; Tolerance: 10%; Voltage: 25V; Wattage: NA; Weight: 0.33mg; Datasheet: Y:\MIS_DATABASE\DATASHEETS\CAPACITORS\GRM033R61E103KA12.PDF
J47 = HEADER_2X1: CON HDR 2X1 2.54MM PITCH ST TH; Chkd/date: VASANTHA/060117; Crtd /date: MAZHAR/280405; Custom_Duty: 24%; Customs_HS_Code: 85369090; Distributor_name: DIGIKEY; Distributor_part_number: WM4000-ND; Footprint Path: Y:\MIS_DATABASE\Library\ALTIUM_TOOL\PCB_FOOTPRINTS\Altium_Footprint_Lib.PcbLib; Height: 10.79MM; Library Path: Y:\MIS_DATABASE\Library\ALTIUM_TOOL\SCHEMATICS_PARTS\MS_Connector_Library.schlib; Mfr_name: MOLEX; Mfr_part_number: 22-03-2021; Mistral Part No: 150009030246-R; Package: THRU-HOLE; Part_type: CONNECTOR\HEADERS; Project: FPGA EXTENDER CARD; RoHS: RoHS; Temperature: -0°C+75°C; Tolerance: NA; Voltage: NA; Wattage: NA; Weight: 139gm; Datasheet: Y:\MIS_DATABASE\DATASHEETS\CONNECTORS\HEADER_X4030.PDF
R81 R88 R231 R232 R239 R242 R244 R248 R250 R257 R259 R271 R273 R275 R277 R279 R281 R284 R286 R290 R292 R294 R296 R302 R306 R441 R540 R601-R603 R626-R629 R631-R638 R642-R645 R668 R768 = RESISTOR: RES 1K 1/20W 5% 0201; Chkd/date: JEBRAN/110815; Crtd /date: JEBRAN/110815; Custom_Duty: 15%; Customs_HS_Code: 85332119; Distributor_name: DIGIKEY; Distributor_part_number: 541-1.00KAABCT-ND; Height: 0.28MM; Mfr_name: VISHAY; Mfr_part_number: CRCW02011K00FKED; Mistral Part No: 110015080014-R; Package: 0201; Part_type: RESISTORS\FIXED; Project: OCTASIC_3000; RoHS: RoHS; Temperature: -55°C+155°C; Tolerance: 5%; Voltage: NA; Wattage: 1/20W; Weight: NA; Datasheet: Y:\MIS_DATABASE\DATASHEETS\RESISTORS\CRCW0201.PDF
R82 R83 R87 R228 R230 R240 R243 R245 R249 R251 R258 R260 R272 R274 R276 R278 R280 R282 R285 R287 R291 R293 R295 R297 R301 R305 R442 R546 R669 = RESISTOR: RES 100K 1/16W 5% 0402; Chkd/date: VASANTHA/061216; Crtd /date: BAVISH/010611; Custom_Duty: 15%; Customs_HS_Code: 85332119; Distributor_name: DIGIKEY; Distributor_part_number: 541-100KJCT-ND; Height: 0.40MM; Mfr_name: VISHAY; Mfr_part_number: CRCW0402100KJNED; Mistral Part No: 110011060002-R; Package: 0402; Part_type: RESISTORS\FIXED; Project: AM4515_EVM_LCD; RoHS: RoHS; Temperature: -55°C+155°C; Tolerance: 5%; Voltage: NA; Wattage: 1/16W; Weight: 0.65mg; Datasheet: Y:\MIS_DATABASE\DATASHEETS\RESISTORS\CRCW0603.PDF
R84 = RESISTOR: RES 1K 1/16W 5% 0402; Crtd /date: BAVISH/021210; Distributor_name: DIGIKEY; Distributor_part_number: 541-1.0KJCT-ND; Footprint Path: VALUE IS VAILABLE 2 TIMES; Height: 0.40MM; Mfr_name: VISHAY; Mfr_part_number: CRCW04021K00JNED; Mistral Part No: 110010120017-R; Package: 0402; Part_type: RESISTORS\FIXED; Project: TE4; RoHS: RoHS; Temperature: -55°C+155°C; Tolerance: 5%; Voltage: NA; Wattage: 1/16W; Weight: NA; Datasheet: Y:\MIS_DATABASE\DATASHEETS\RESISTORS\CRCW0603.PDF
SW2 SW3 = SW10_218-10LPST: SWITCH DIP SPST HALF PITCH 10POS SMD; Chkd/date: VASANTHA/250816; Crtd /date: VASANTHA/250816; Custom_Duty: 24%; Customs_HS_Code: 85369090; Distributor_name: DIGIKEY; Distributor_part_number: CT21810LPST-ND; Height: 2.65MM; Mfr_name: CTS; Mistral Part No: 130016080032-R; Package: SMD; Part_type: ELECTRO-MECHANICAL\SWITCH; Project: EPOS_EVM; RoHS: RoHS; Temperature: -55°C+85°C; Tolerance: NA; Voltage: NA; Wattage: NA; Weight: NA; Datasheet: Y:\MIS_DATABASE\DATASHEETS\MISC\SWITCHES\128-12LPST.PDF
SW4 = SW4_CHS-02TA: SWITCH SLIDE 2PST SMD; Chkd/date: MAZHAR/021211; Crtd /date: CHAITHANYA/021211; Custom_Duty: 24%; Customs_HS_Code: 85369090; Distributor_name: DIGIKEY; Distributor_part_number: 563-1005-1-ND; Height: 2.50MM; Mfr_name: COPAL ELECTRONICS; Mfr_part_number: CHS-02TA; Mistral Part No: 130011120001-R; Package: SMD; Part_type: ELECTRO-MECHANICAL\SWITCH; Project: AVCDP1; RoHS: RoHS; Temperature: -40°C+85°C; Tolerance: NA; Voltage: NA; Wattage: NA; Weight: 0.08g; Datasheet: Y:\MIS_DATABASE\DATASHEETS\MISC\SWITCHES\CHSSER.PDF
SW9 = SW8_BD04: SWITCH DIP SPST 4POS ST SMD; Chkd/date: MANIRAJA/040619; Crtd /date: VASANTHA/241221; Custom_Duty: 24%; Customs_HS_Code: 85369090; Distributor_name: DIGIKEY; Distributor_part_number: CT3110CT-ND; Footprint Path: Y:\MIS_DATABASE\Library\ALTIUM_TOOL\PCB_FOOTPRINTS\Altium_Footprint_Lib.PcbLib; Height: 2.65MM; Library Path: Y:\MIS_DATABASE\Library\ALTIUM_TOOL\SCHEMATICS_PARTS\MS_SWITCH_Library.schlib; Mfr_name: CTS; Mfr_part_number: 218-4LPSTR; Mistral Part No: 130014120039-R; Package: SMD; Part_type: ELECTRO-MECHANICAL\SWITCH; Project: FREE SCALE POM; RoHS: RoHS; Temperature: -55°C+85°C; Tolerance: NA; Voltage: NA; Wattage: NA; Weight: NA; Datasheet: Y:\MIS_DATABASE\DATASHEETS\MISC\SWITCHES\128-XXLPST.PDF
U17 = SN74LVC1G32DBVR_SOT23-5: IC SINGAL 2 INPUT POSITIVE OR GATE SOT23-5; Chkd/date: MANIRAJA/051017; Crtd /date: MAZHAR/070806; Custom_Duty: 15%; Customs_HS_Code: 85423100; Distributor_name: DIGIKEY; Distributor_part_number: 296-9847-1-ND; Height: 1.45MM; Mfr_name: TEXAS INSTRUMENTS; Mistral Part No: 141009030236-R; Package: SOT23-5; Part_type: ICS\DIGITAL\GATES; Project: SVDO_RMB_MMA; RoHS: RoHS; Temperature: -40°C+85°C; Tolerance: NA; Voltage: NA; Wattage: NA; Weight: 6.3mg; Datasheet: Y:\MIS_DATABASE\DATASHEETS\ICS\DIGITAL\GATES\SN74LVC1G32.PDF
U95 = SN74AVC4T245RGYR_QFN16: IC 4-BIT DUAL SUPPLY BUS TRANSCEIVER QFN16; Chkd/date: MAZHAR/060308; Crtd /date: USMAN/060308; Custom_Duty: 15%; Customs_HS_Code: 85423100; Distributor_name: DIGIKEY; Distributor_part_number: 296-18231-1-ND; Height: 1.00MM; Mfr_name: TEXAS INSTRUMENTS; Mistral Part No: 141009030112-R; Package: QFN16; Part_type: ICS\DIGITAL\COMBINATIONAL; Project: HS100RD; RoHS: Sb/ Br FREE; Datasheet: Y:\MIS_DATABASE\DATASHEETS\ICS\DIGITAL\BUSTRANSCEIVER\SN74AVC4T245XXXX.PDF
U99 = TCA6424ARGJR_QFN32: IC I2C I/O EXPANDER 24B UQFN32; Chkd/date: NAVEED/100715; Crtd /date: NAVEED/100914; Custom_Duty: 15%; Customs_HS_Code: 85423100; Distributor_name: DIGIKEY; Distributor_part_number: 296-27844-1-ND; Height: 0.60MM; Mfr_name: TEXAS INSTRUMENTS; Mistral Part No: 141014090009-R; Package: UQFN32; Part_type: ICS\DIGITAL\BUSTRANSCEIVER; Project: ZK_BIOMETRIC; RoHS: RoHS; Temperature: -40°C+85°C; Weight: NA; Datasheet: Y:\MIS_DATABASE\DATASHEETS\ICS\DIGITAL\BUSTRANSCEIVER\TCA6424AR.PDF
U102 U105 = SN74AVC8T245RHL_QFN24: IC BUS TRANSCEIVER 8-BIT DUAL-SUPPLY QFN24; Chkd/date: VASANTHA/231216; Crtd /date: BAVISH/290411; Custom_Duty: 15%; Customs_HS_Code: 85423100; Distributor_name: DIGIKEY; Distributor_part_number: 296-17859-1-ND; Height: 1.00MM; Mfr_name: TEXAS INSTRUMENTS; Mfr_part_number: SN74AVC8T245RHLR; Mistral Part No: 143011040001-R; Package: QFN24; Part_type: ICS\TELECOM\TRANSCEIVER; Project: OMAPL1_PEC20; RoHS: RoHS; Temperature: -40°C+85°C; Tolerance: NA; Voltage: NA; Wattage: NA; Weight: NA; Datasheet: Y:\MIS_DATABASE\DATASHEETS\ICS\DIGITAL\BUSTRANSCEIVER\SN74AVC8T245.PDF

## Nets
DGND: C101.2 C102.2 C109.2 C110.2 C111.2 C117.2 C120.2 C123.2 C124.2 C358.2 C371.2 C372.2 C378.2 C381.2 C388.2 C392.2 C393.2 C394.2 C399.2 C400.2 C403.2 C404.2 C405.2 C613.2 C614.2 C624.1 C631.2 C632.2 C635.2 C636.2 C673.2 C674.2 C686.2 C719.2 C720.2 J12.1(CH-GND) J41.7 J41.16 J41.25 J41.34 J41.40 J41.41 J41.42 Q3.2(S) Q4.2(S) Q9.2(S) R82.2 R83.2 R87.2 R91.2 R92.2 R95.2 R96.2 R99.2 R112.2 R122.2 R135.2 R228.2 R230.2 R240.2 R243.2 R245.2 R249.2 R251.2 R258.2 R260.2 R272.2 R274.2 R276.2 R278.2 R280.2 R282.2 R285.2 R287.2 R291.2 R293.2 R295.2 R297.2 R301.2 R305.2 R409.1 R417.2 R442.2 R456.2 R546.2 R596.1 R622.1 R648.1 R669.2 R768.2 U17.3(GND) U22.49(GND) U82.3(GND) U95.8(GND1) U95.9(GND2) U95.17(PAD) U99.25(GND) U99.33(EP) U102.11(GND1) U102.12(GND2) U102.13(GND3) U102.25(EP) U105.11(GND1) U105.12(GND2) U105.13(GND3) U105.25(EP) U126.4(GND) ; also on sheet 11 12 13 14 15 16 17 18 19 20 21 22 26 27 28 29 30 31 32 33 34 35 36 37 38 39 40 41 42 43 44
VCC1V8: C102.1 C120.1 C123.1 C358.1 C371.1 C394.1 C400.1 C404.1 FL11.1 R90.1 R93.1 R94.1 R97.1 R98.2 R100.2 R115.1 R119.1 R149.1 R156.2 U22.19(VDDIO) U22.30(VDDIO) U22.41(VDDIO) U82.5(VCC) ; also on sheet 11 18 19 20 21 22 26 29 31 33 35 36 37 38 41 44
VCC3V3_IO: C613.1 C631.1 C636.1 C720.1 R78.2 R79.2 R81.1 R84.1 R88.1 R231.1 R232.1 R239.1 R242.1 R244.1 R248.1 R250.1 R257.1 R259.1 R271.1 R273.1 R275.1 R277.1 R279.1 R281.1 R284.1 R286.1 R290.1 R292.1 R294.1 R296.1 R302.1 R306.1 R412.2 R441.1 R449.1 R540.1 R668.1 U95.16(VCCB) U102.23(VCCB1) U102.24(VCCB2) U105.23(VCCB1) U105.24(VCCB2) U126.8(VCCB) ; also on sheet 11 18 19 20 21 22 26 28 29 30 31 33 34 35 36 37 38 39 41 42 43 44
VCC3V3_TA: C614.1 C624.2 C632.1 C635.1 C673.1 C674.1 C686.1 C719.1 J41.1 J41.2 J41.3 R66.1 R630.2 R656.2 R681.2 R682.2 R683.2 R684.2 R685.2 R696.1 R697.1 R773.2 R774.1 R775.1 R778.2 U17.5(VCC) U95.1(VCCA) U99.27(VCCP) U99.31(VCC) U102.1(VCCA) U105.1(VCCA) U126.1(VCCA) ; also on sheet 43
VDD_1V0: C101.1 C110.1 C111.1 C124.1 C372.1 C388.1 C392.1 C399.1 C403.1 U22.6(VDD1P0) U22.24(VDD1P0) U22.31(VDD1P0) U22.42(VDD1P0) ; also on sheet 13 21 22 33 35 42
VDD_2V5: C109.1 C117.1 C378.1 C381.1 C393.1 U22.3(VDDA2P5) U22.9(VDDA2P5) ; also on sheet 21 22 33 42
ADDR: R622.2 U99.26(ADDR)
BOOTMODE_I2C_SCL: J41.37 R696.2 U99.29(SCL)
BOOTMODE_I2C_SDA: J41.39 R697.2 U99.30(SDA)
BOOTMODEON: U17.4(Y) U95.14(~{2OE}) U95.15(~{1OE}) U102.22(~{OE}) U105.22(~{OE})
DIR: R648.2 R656.1 U95.2(1DIR) U95.3(2DIR) U102.2(DIR) U105.2(DIR)
GPIO_MCU_RGMII_RSTN: R409.2 R412.1 U82.1(A) ; also on sheet 37
MCU_BOOTMODE0: R228.1 R231.2 ; also on sheet 34 37
MCU_BOOTMODE1: R540.2 R546.1 ; also on sheet 34 37
MCU_BOOTMODE2: R230.1 R232.2 ; also on sheet 34
MCU_BOOTMODE3: R301.1 SW4.1(A1) ; also on sheet 34
MCU_BOOTMODE9: R83.1 R84.2 ; also on sheet 34
MCU_EARTH: C405.1 J12.15(SH1) J12.16(SH2) R456.1
MCU_ETH1_CLK_OUT: TP14.1(TP) U22.18(CLK_OUT)
MCU_ETH1_INTn: R100.1 U22.44(INT/PWDN) ; also on sheet 38
MCU_ETH1_RBIAS: R135.1 U22.12(RBIAS)
MCU_ETH1_RESETn: R417.1 U22.43(RESET_N) U82.4(Y)
MCU_ETH_D0M: J12.10(MX0-) U22.2(TD_M_A)
MCU_ETH_D0P: J12.9(MX0+) U22.1(TD_P_A)
MCU_ETH_D1M: J12.8(MX1-) U22.5(TD_M_B)
MCU_ETH_D1P: J12.7(MX1+) U22.4(TD_P_B)
MCU_ETH_D2M: J12.6(MX2-) U22.8(TD_M_C)
MCU_ETH_D2P: J12.5(MX2+) U22.7(TD_P_C)
MCU_ETH_D3M: J12.4(MX3-) U22.11(TD_M_D)
MCU_ETH_D3P: J12.3(MX3+) U22.10(TD_P_D)
MCU_ETH_GPIO_0: R72.2 R96.1 R97.2 U22.39(GPIO_0)
MCU_ETH_GPIO_1: R94.2 R95.1 U22.40(GPIO_1)
MCU_ETH_LED1: J12.12 Q9.3(D)
MCU_ETH_LED2: J12.13 Q3.3(D) R79.1
MCU_ETH_LED3: J12.14 Q4.3(D) R78.1
MCU_ETH_LED_1000: R73.2 R90.2 R91.1 U22.46(LED_1)
MCU_ETH_LED_ACTn: R92.1 R93.2 R451.2 U22.45(LED_2)
MCU_MCAN1_TX/BOOTMODE4: R305.1 SW4.2(A2) ; also on sheet 34
MCU_MDC_RGMII_1V8: R149.2 U22.16(MDC) ; also on sheet 34
MCU_MDIO_1V8: R156.1 U22.17(MDIO) ; also on sheet 34
MCU_PORz_OUT: U82.2(B) ; also on sheet 34
MCU_RGMII1_CLKIN: U22.15(XI) ; also on sheet 36
MCU_RGMII1_RD0: R118.1 U34.L6(MCU_RGMII1_RD0)
MCU_RGMII1_RD0_R: R118.2 R119.2 R122.1 U22.33(RX_D0)
MCU_RGMII1_RD1: R114.1 U34.M6(MCU_RGMII1_RD1)
MCU_RGMII1_RD1_R: R114.2 U22.34(RX_D1)
MCU_RGMII1_RD2: R111.1 U34.L5(MCU_RGMII1_RD2)
MCU_RGMII1_RD2_R: R111.2 R112.1 R115.2 U22.35(RX_D2)
MCU_RGMII1_RD3: R102.1 U34.L2(MCU_RGMII1_RD3)
MCU_RGMII1_RD3_R: R102.2 U22.36(RX_D3)
MCU_RGMII1_RX_CTL: R101.1 U34.N5(MCU_RGMII1_RX_CTL)
MCU_RGMII1_RX_CTL_R: R98.1 R99.1 R101.2 U22.38(RX_DV/RX_CTRL)
MCU_RGMII1_RXC: R121.1 U34.M1(MCU_RGMII1_RXC)
MCU_RGMII1_RXC_R: R121.2 U22.32(RX_CLK)
MCU_RGMII1_TD0: RA7.4 U22.28(TX_D0)
MCU_RGMII1_TD0_R: RA7.5 U34.M5(MCU_RGMII1_TD0)
MCU_RGMII1_TD1: RA7.3 U22.27(TX_D1)
MCU_RGMII1_TD1_R: RA7.6 U34.M4(MCU_RGMII1_TD1)
MCU_RGMII1_TD2: RA7.2 U22.26(TX_D2)
MCU_RGMII1_TD2_R: RA7.7 U34.M3(MCU_RGMII1_TD2)
MCU_RGMII1_TD3: RA7.1 U22.25(TX_D3)
MCU_RGMII1_TD3_R: RA7.8 U34.M2(MCU_RGMII1_TD3)
MCU_RGMII1_TX_CTL: R439.2 U22.37(TX_EN/TX_CTRL)
MCU_RGMII1_TX_CTL_R: R439.1 U34.N4(MCU_RGMII1_TX_CTL)
MCU_RGMII1_TXC: R438.2 U22.29(GTX_CLK)
MCU_RGMII1_TXC_R: R438.1 U34.N1(MCU_RGMII1_TXC)
MCU_SPI0_CLK/BOOTMODE6: R442.1 SW9.2 ; also on sheet 34
MCU_SPI0_D0/BOOTMODE7: R669.1 SW9.3 ; also on sheet 34 44
PORz_OUT: U17.1(A) ; also on sheet 19 21 33 34 35 44
PRG2_ETH1_LED_LINK/MCUBOOTMODE5: R87.1 SW9.1 ; also on sheet 21 34
PRG2_ETH2_LED_LINK/MCUBOOTMODE8: R82.1 SW9.4 ; also on sheet 22 34
SoC_I2C2_SCL: U126.7(SCLB) ; also on sheet 20 26 44
SoC_I2C2_SDA: U126.6(SDAB) ; also on sheet 20 26 44
SoC_I2C2_TA_SCL: J41.36 R775.2 U126.2(SCLA)
SoC_I2C2_TA_SDA: J41.38 R774.2 U126.3(SDAA)
SYS_BOOTMODE0: U99.1(P00) U102.3(A1)
SYS_BOOTMODE1: U99.2(P01) U102.4(A2)
SYS_BOOTMODE2: U99.3(P02) U102.5(A3)
SYS_BOOTMODE3: U99.4(P03) U102.6(A4)
SYS_BOOTMODE4: U99.5(P04) U102.7(A5)
SYS_BOOTMODE5: U99.6(P05) U102.8(A6)
SYS_BOOTMODE6: U99.7(P06) U102.9(A7)
SYS_BOOTMODE7: U99.8(P07) U102.10(A8)
SYS_BOOTMODE8: U99.9(P10) U105.3(A1)
SYS_BOOTMODE9: U99.10(P11) U105.4(A2)
SYS_BOOTMODE10: U99.11(P12) U105.5(A3)
SYS_BOOTMODE11: U99.12(P13) U105.6(A4)
SYS_BOOTMODE12: U99.13(P14) U105.7(A5)
SYS_BOOTMODE13: U99.14(P15) U105.8(A6)
SYS_BOOTMODE14: U99.15(P16) U105.9(A7)
SYS_BOOTMODE15: U99.16(P17) U105.10(A8)
SYS_BOOTMODE16: U95.4(1A1) U99.19(P22)
SYS_BOOTMODE17: U95.5(1A2) U99.18(P21)
SYS_BOOTMODE18: U95.6(2A1) U99.17(P20)
TCA6424_EXP_INT: R630.1 U99.32(~{INT})
TEST_GPIO1: R683.1 R692.1 ; also on sheet 11
TEST_GPIO2: R684.1 R693.1 ; also on sheet 11
TEST_GPIO3: R694.1 R773.1 TP90.1(TP)
TEST_GPIO4: R685.1 R695.1 TP65.1(TP) U99.28(~{RESET})
TEST_PORZn: R681.1 R690.1 ; also on sheet 39
TEST_POWERDOWN: R689.1 ; also on sheet 43
TEST_WARMRESETn: R682.1 R691.1 ; also on sheet 11
VOUT_D0_BOOTMODE0: R297.1 R631.1 SW3.1 ; also on sheet 44
VOUT_D1_BOOTMODE1: R293.1 R626.1 SW3.2 ; also on sheet 44
VOUT_D2_BOOTMODE2: R287.1 R632.1 SW3.3 ; also on sheet 44
VOUT_D3_BOOTMODE3: R282.1 R627.1 SW3.4 ; also on sheet 44
VOUT_D4_BOOTMODE4: R278.1 R633.1 SW3.5 ; also on sheet 44
VOUT_D5_BOOTMODE5: R274.1 R628.1 SW3.6 ; also on sheet 44
VOUT_D6_BOOTMODE6: R260.1 R629.1 SW3.7 ; also on sheet 44
VOUT_D7_BOOTMODE7: R251.1 R634.1 SW3.8 ; also on sheet 44
VOUT_D8_BOOTMODE8: R245.1 R642.1 SW3.9 ; also on sheet 44
VOUT_D9_BOOTMODE9: R240.1 R635.1 SW3.10 ; also on sheet 44
VOUT_D10_BOOTMODE10: R295.1 R643.1 SW2.1 ; also on sheet 44
VOUT_D11_BOOTMODE11: R291.1 R636.1 SW2.2 ; also on sheet 44
VOUT_D12_BOOTMODE12: R285.1 R644.1 SW2.3 ; also on sheet 44
VOUT_D13_BOOTMODE13: R280.1 R637.1 SW2.4 ; also on sheet 44
VOUT_D14_BOOTMODE14: R276.1 R638.1 SW2.5 ; also on sheet 44
VOUT_D15_BOOTMODE15: R272.1 R645.1 SW2.6 ; also on sheet 44
VOUT_D17_BOOTMODE16: R258.1 R603.1 SW2.7 ; also on sheet 44
VOUT_D18_BOOTMODE17: R249.1 R602.1 SW2.8 ; also on sheet 44
VOUT_D19_BOOTMODE18: R243.1 R601.1 SW2.9 ; also on sheet 44
N15365714: J41.27 R690.2
N15365947: J41.30 R692.2
N15366015: J41.31 R693.2
N15366091: J41.32 R694.2
N15584817: R281.2 SW3.17
N15584821: R286.2 SW3.18
N15584825: R292.2 SW3.19
N15584829: R296.2 SW3.20
N15591045: R250.2 SW3.13
N15591049: R259.2 SW3.14
N15591053: R273.2 SW3.15
N15591057: R277.2 SW3.16
N15697942: J12.11 R449.2
N15698204: TP12.1(TP) U22.13(VDDA1P8) U22.48(VDDA1P8)
N16295803: R244.2 SW3.12
N16300126: R239.2 SW3.11
N16303893: R279.2 SW2.17
N16303897: R284.2 SW2.18
N16303901: R290.2 SW2.19
N16303905: R294.2 SW2.20
N16303913: R248.2 SW2.13
N16303917: R257.2 SW2.14
N16303921: R271.2 SW2.15
N16303925: R275.2 SW2.16
N16303929: R242.2 SW2.12
N16865678: FL11.2 J12.2(VCC)
N17211229: J41.33 R695.2
N17546132: J41.26 R689.2
N17546158: J41.28 R691.2
N17903256: R302.2 SW4.4(B1)
N17903258: R306.2 SW4.3(B2)
N17976903: R596.2 U95.7(2A2)
N18070254: R603.2 U95.13(1B1)
N18070257: R602.2 U95.12(1B2)
N18070260: R601.2 U95.11(2B1)
N18122515: Q3.1(G) R73.1
N18122533: Q4.1(G) R72.1
N18122581: Q9.1(G) R451.1
N18867275: R642.2 U105.21(B1)
N18867277: R635.2 U105.20(B2)
N18867279: R643.2 U105.19(B3)
N18867281: R636.2 U105.18(B4)
N18867283: R644.2 U105.17(B5)
N18867285: R637.2 U105.16(B6)
N18867287: R638.2 U105.15(B7)
N18867289: R645.2 U105.14(B8)
N18867885: R631.2 U102.21(B1)
N18867903: R626.2 U102.20(B2)
N18867905: R632.2 U102.19(B3)
N18867915: R627.2 U102.18(B4)
N18867925: R633.2 U102.17(B5)
N18867943: R628.2 U102.16(B6)
N18867953: R629.2 U102.15(B7)
N18867955: R634.2 U102.14(B8)
N23068969: R668.2 SW9.6
N23068970: R88.2 SW9.8
N23068971: R81.2 SW9.5
N23068972: R441.2 SW9.7
N23474700: J47.1 R66.2 U17.2(B)
N23475552: J47.2 R768.1
N23514459: R778.1 U126.5(EN)

Not connected (* = marked no-connect by the designer): J41 4* 5* 6* 8* 9* 10* 11* 12* 13* 14* 15* 17* 18* 19* 20* 21* 22* 23* 24* 29* 35*; SW2 10* 11*; U22 14(XO)* 20(JTAG_CLK)* 21(JTAG_TDO)* 22(JTAG_TMS)* 23(JTAG_TDI)* 47(LED_0)*; U95 10(2B2)*; U99 20(P23)* 21(P24)* 22(P25)* 23(P26)* 24(P27)*

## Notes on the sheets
sheet 23
- RGMII ETHERNET PHY - MCU
- MCU_RGMII
- STRAPPING
- PHY_RESET
- RJ45 with Integrated Mangnetics
- PHY ADDRESS = 00000
- MCU SPEED & ACTIVITY  LED DRIVERS
sheet 24
- TEST AUTOMATION
- 40-PIN AUTOMATION HEADER
- TEST AUTOMATION  GPIO MAPPING
- Direction WRT CTRL
- Internal/
  External
  PU/PD states
- SIGNAL NAME
- DESCRIPTION
- OUTPUT
  OUTPUT
  OUTPUT
  OUTPUT
  OUTPUT
  OUTPUT
  OUTPUT
- TEST_POWERDOWN
  TEST_PORZn
  TEST_WARMRESETn
  TEST_GPIO1
  TEST_GPIO2
  TEST_GPIO3
  TEST_GPIO4
- Used to Power down the OVP Circuit
  Used to  Reset the SoC PORz
  Used to Reset the SoC Warmreset
  Used to Generate the interrupt on
  WKUP_GPIO0_13_INTn Pin
  Used to Generate the interrupt on
  WKUP_GPIO0_27_INTn
  Used to Enable the BOOTMODE Buffer
  Used to Reset the Bootmode IO Expander
- External Pullup
  External Pullup
  External Pullup
  External Pullup
  External Pullup
  External Pullup
  External Pullup
sheet 25
- BOOT MODE BUFFER & SWITCHES
- DIR = H: A -> B
  DIR = L: B -> A
  OE = H: output = Hi-Z
- DIR = H: A -> B
  DIR = L: B -> A
  OE = H: output = Hi-Z
- I2C ADDRESS: 0x22
- SWITCH ON  =  LOGIC 1
  SWITCH OFF =  LOGIC 0
- BOOT MODES SUPPORTED
- 1. OSPI
- 2. MMC1 - SD CARD
- 3. MMC0 - eMMC
- 4. PCIE (endpoint)
- 5. CPSW Ethernet Slave
- 6. USB Host
- 7. USB Device
